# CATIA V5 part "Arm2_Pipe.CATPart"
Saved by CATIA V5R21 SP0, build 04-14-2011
Part number: Arm2_Pipe
Bounding box of the stored display mesh (mm): x 0 to 180, y -12.5 to 12.5, z -12.5 to 12.5
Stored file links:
  F:\教程\Robotic_Arm_Arduino_Kinect\机械臂CAD\Arm_Detailed_Design_Assembly\Arm2_Pipe.CATPart
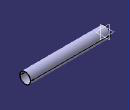
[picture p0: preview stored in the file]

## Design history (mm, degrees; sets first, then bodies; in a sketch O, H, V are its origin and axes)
Body1 (main body)
  Sketch1 on yz-plane, origin (0, 0, 0), H (0, 1, 0), V (0, 0, 1)
    circle A1 centre (0, 0) radius 11.5
    circle A2 centre (0, 0) radius 12.5
    radius A1 = 11.5
    radius A2 = 12.5
  Pad1: profile Sketch1, direction (1, 0, 0), length 180
  Sketch2 on zx-plane, origin (0, 0, 0), H (-1, 0, 0), V (0, 0, 1)
    circle A1 centre (-6, 0) radius 1.25
    point P1 (-6, 0)
    circle A2 centre (-174, 0) radius 1.25
    point P2 (-174, 0)
    reference projected line E1 (-180, -12.5) -> (-180, 12.5) from edge [face of Pad1 from Sketch1.A2 | end face of Pad1]
    radius A1 = 1.25
    distance V P1 = 6
    radius A2 = 1.25
    distance E1 P2 = 6
    coincidence: P1 H, P2 H
  Pocket1: profile Sketch2, direction (0, -1, 0), length 50, mirrored extent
